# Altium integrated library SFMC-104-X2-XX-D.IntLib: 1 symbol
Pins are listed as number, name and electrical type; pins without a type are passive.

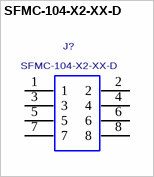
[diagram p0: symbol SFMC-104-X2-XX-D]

## SFMC-104-X2-XX-D
designator J?
0.050" CUTTABLE SOCKET STRIP, DOUBLE ROW ASSEMBLY.; MANUFACTURER: SAMTEC
footprint SFMC-104-X2-XX-D
pins: 1, 2, 3, 4, 5, 6, 7, 8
